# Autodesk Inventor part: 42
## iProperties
Created: 2011-11
Part Number: 42
Document SubType Name: Modeling
Designer: D Cole
Density: 1 g/cm^3
Author: D Cole
Translation Standard: STEP AP214IS
File Name: P:\Fastrack\53972_CRANE 3D\Press Fit\HATTERSLEY\100-TH\42MM\42.stp
Preprocessor: Autodesk Inventor 2008
Postprocessor: Build: 342, Release: 2008 SP3 - Date: Tue 05/27/2008
Sent Units: MILLIMETERS
Uncertainty: 0.01
